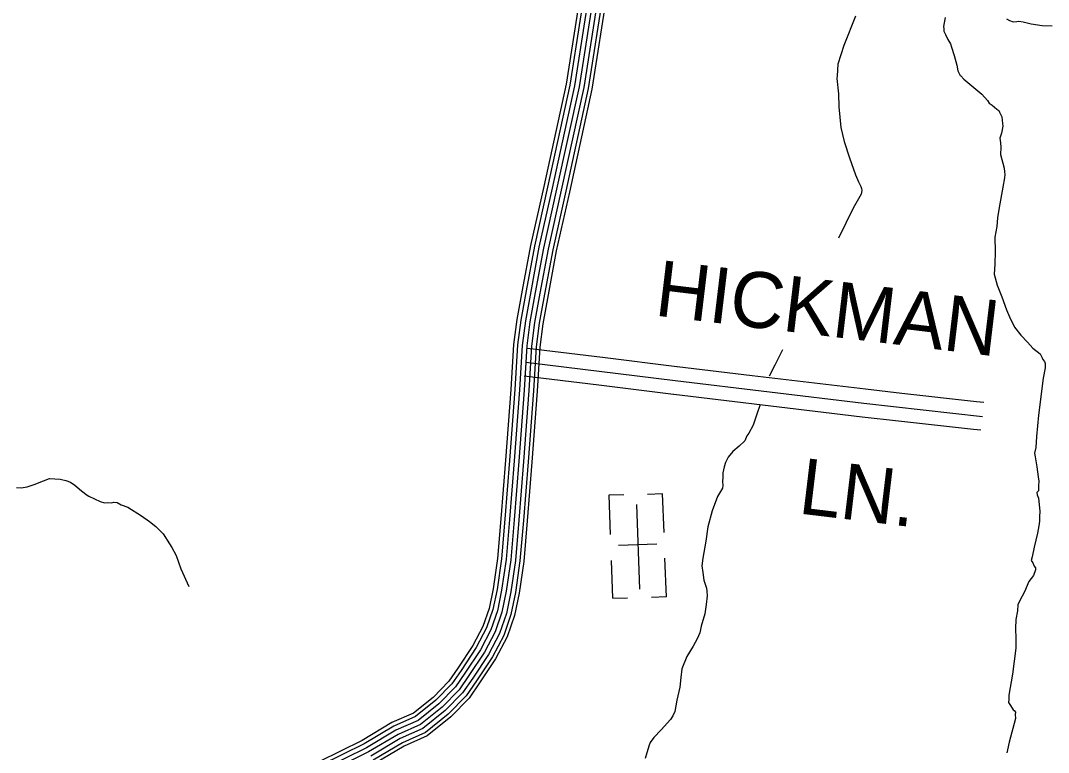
# Model space of a CAD drawing. Extents: x 1551132 to 1791609, y 378168 to 563823.
# Drawn here: x 1653929 to 1660744, y 437892 to 442743 of the extents above; entities that cross this region are included whole.
import ezdxf

# ---------------------------------------------------------------- set-up
doc = ezdxf.new("R2010")
doc.units = 0
for name, color, linetype in [('DESIGN - ROW - Right-of-Way and Easement Labels', 7, 'Continuous'), ('DESIGN - TRANSPORTATION - Text', 7, 'Continuous'), ('DESIGN - UTILITIES - Cable (Underground) with Text', 7, 'Continuous'), ('SURVEY - CENTERLINE - Preliminary Text', 7, 'Continuous'), ('SURVEY - PROPERTY - Owners', 7, 'Continuous')]:
    doc.layers.add(name, color=color, linetype=linetype)

msp = doc.modelspace()

# ---------------------------------------------------------------- linework, layer by layer
at = {"layer": 'DESIGN - TRANSPORTATION - Text'}
for points in [[(1659464.746, 442771.948), (1659388.681, 442578.526), (1659347.349, 442454.814), (1659342.482, 442376.771), (1659340.282, 442358.77), (1659353.124, 442256.493), (1659354.165, 442170.365), (1659368.623, 442034.028), (1659389.564, 441941.676), (1659424.305, 441833.148), (1659464.996, 441720.554), (1659484.454, 441674.277), (1659500.095, 441644.06), (1659503.928, 441630.001), (1659507.77, 441615.943), (1659503.503, 441591.959), (1659450.529, 441498.414), (1659352.423, 441301.576)], [(1660059.891, 442763.389), (1660049.233, 442703.421), (1660051.049, 442687.379), (1660050.891, 442673.37), (1660062.632, 442651.212), (1660078.232, 442616.994), (1660093.89, 442588.785), (1660101.64, 442566.668), (1660118.989, 442510.4), (1660136.264, 442448.131), (1660143.83, 442409.997), (1660151.622, 442391.888), (1660159.472, 442379.779), (1660163.421, 442375.729), (1660183.171, 442355.487), (1660301.91, 442256.051), (1660339.384, 442213.584), (1660351.167, 442195.425), (1660370.983, 442181.191), (1660402.649, 442154.807), (1660416.54, 442146.64), (1660420.424, 442136.59), (1660436.04, 442104.372), (1660439.54, 442060.28), (1660441.34, 442042.229), (1660432.84, 441996.27), (1660422.49, 441964.335), (1660426.132, 441932.251), (1660427.815, 441904.201), (1660427.257, 441854.141), (1660450.214, 441763.764), (1660453.939, 441739.696), (1660455.764, 441723.654), (1660453.498, 441699.645), (1660442.815, 441637.677), (1660417.348, 441503.782), (1660406.607, 441435.813), (1660401.965, 441377.787), (1660389.199, 441307.835), (1660390.124, 441211.691), (1660389.182, 441127.597), (1660384.449, 441061.562), (1660403.615, 440989.252), (1660434.698, 440910.808), (1660465.714, 440826.356), (1660485.171, 440780.079), (1660518.371, 440711.619), (1660561.703, 440657.068), (1660605.127, 440610.533), (1660640.651, 440572.091), (1660690.158, 440533.49), (1660701.85, 440507.331), (1660707.733, 440497.256), (1660717.557, 440483.122), (1660723.391, 440469.046), (1660723.166, 440449.021), (1660723.082, 440441.012), (1660710.341, 440373.061), (1660677.633, 440127.096), (1660666.075, 439987.034), (1660661.258, 439912.99), (1660652.842, 439875.031), (1660656.567, 439850.955), (1660667.817, 439784.745), (1660677.066, 439718.56), (1660680.741, 439690.476), (1660678.391, 439658.459), (1660678.033, 439626.424), (1660667.908, 439614.516), (1660669.75, 439600.482), (1660677.5, 439578.365), (1660686.499, 439490.146), (1660684.099, 439454.128), (1660685.758, 439424.069), (1660681.433, 439394.077), (1660672.908, 439346.109), (1660649.883, 439252.24), (1660637.184, 439188.296), (1660628.926, 439164.354), (1660640.734, 439148.204), (1660650.475, 439126.061), (1660658.35, 439115.961), (1660658.191, 439101.944), (1660645.783, 439064.035), (1660615.384, 439024.317), (1660586.66, 438956.54), (1660554.06, 438898.822), (1660541.761, 438870.921), (1660539.319, 438830.895), (1660528.686, 438772.935), (1660526.011, 438712.884), (1660527.278, 438646.782), (1660528.553, 438582.68), (1660506.661, 438410.701), (1660481.129, 438270.789), (1660482.812, 438242.738), (1660480.595, 438222.738), (1660492.353, 438202.579)], [(1660467.273, 442754.889), (1660485.114, 442742.681), (1660510.989, 442734.381), (1660534.98, 442736.122), (1660549.004, 442739.972), (1660576.895, 442733.656), (1660630.686, 442721.047), (1660702.476, 442710.247), (1660768.357, 442707.513)], [(1658982.007, 440561.048), (1658929.574, 440458.77), (1658893.067, 440385.727)], [(1658834.027, 440198.738), (1658808.027, 440127.67), (1658787.319, 440061.81), (1658758.753, 440008.05), (1658744.57, 439990.183), (1658732.204, 439956.274), (1658693.88, 439922.648), (1658651.539, 439887.072), (1658621.156, 439849.354), (1658602.773, 439813.512), (1658594.474, 439785.561), (1658586.04, 439745.601), (1658585.724, 439717.567), (1658583.39, 439687.55), (1658585.099, 439661.499), (1658582.899, 439643.499), (1658550.325, 439587.789), (1658515.317, 439494.045), (1658486.176, 439388.225), (1658473.118, 439292.239), (1658453.893, 439180.303), (1658445.318, 439128.335), (1658452.818, 439084.192), (1658460.243, 439034.041), (1658477.643, 438981.781), (1658479.409, 438961.739)], [(1653900.95, 439649.03), (1653932.883, 439646.671), (1653972.899, 439652.238), (1654019.006, 439667.755), (1654081.213, 439693.098), (1654121.312, 439706.681), (1654157.261, 439706.281), (1654191.193, 439703.906), (1654229.051, 439695.481), (1654260.875, 439683.114), (1654288.608, 439662.78), (1654332.148, 439626.254), (1654369.781, 439597.804), (1654382.531, 439590.587), (1654457.187, 439554.778), (1654485.061, 439546.461), (1654505.053, 439548.244), (1654530.994, 439545.961), (1654547.035, 439551.786), (1654568.96, 439547.544), (1654596.767, 439533.219), (1654640.524, 439516.71), (1654729.772, 439459.659), (1654783.296, 439423.016), (1654824.878, 439390.515), (1654874.277, 439341.906), (1654915.476, 439275.37), (1654931.184, 439251.162), (1654960.542, 439196.768), (1654991.516, 439108.308), (1655044.14, 438991.571)], [(1658479.409, 438961.739), (1658481.051, 438929.672), (1658474.409, 438871.67), (1658465.751, 438811.685), (1658440.852, 438727.85), (1658432.368, 438683.882), (1658415.944, 438644.014), (1658389.444, 438596.238), (1658346.745, 438528.619), (1658313.871, 438446.876), (1658307.23, 438388.866), (1658300.521, 438324.856), (1658279.588, 438238.978), (1658266.755, 438163.018), (1658254.464, 438135.117), (1658238.214, 438111.258), (1658177.516, 438041.84), (1658127.009, 437990.322), (1658104.676, 437958.529), (1658094.426, 437934.612), (1658069.543, 437852.777)], [(1660492.353, 438202.579), (1660510.011, 438174.345), (1660517.961, 438170.253), (1660525.811, 438158.153), (1660523.661, 438144.161), (1660525.344, 438116.101), (1660483.653, 437960.356), (1660473.087, 437908.396), (1660468.895, 437890.421)]]:
    msp.add_lwpolyline(points, dxfattribs=at)
at = {"layer": 'DESIGN - UTILITIES - Cable (Underground) with Text'}
for p, q in [((1657829.832, 439596.335), (1657839.394, 439335.787)), ((1657929.434, 439600.019), (1657830.482, 439596.36)), ((1658186.132, 439605.472), (1658086.496, 439601.863)), ((1658195.46, 439348.916), (1658186.057, 439605.431)), ((1658148.152, 439272.814), (1657894.721, 439263.378)), ((1657845.712, 439164.933), (1657854.857, 438913.627)), ((1658211.04, 438922.707), (1658201.604, 439180.688)), ((1657854.974, 438913.669), (1657953.218, 438917.32)), ((1658210.865, 438922.782), (1658111.421, 438919.064))]:
    msp.add_line(p, q, dxfattribs=at)
msp.add_lwpolyline([(1658012.987, 439535.644), (1658033.702, 438973.031)], dxfattribs=at)
at = {"layer": 'SURVEY - CENTERLINE - Preliminary Text'}
for points in [[(1657751.562, 443633.528), (1657546.149, 442320.477), (1657397.636, 441643.492), (1657310.379, 441252.223), (1657255.864, 440956.607), (1657220.006, 440760.452), (1657198.123, 440595.24), (1657179.765, 440298.573), (1657144.316, 439829.07), (1657113.433, 439441.159), (1657091.675, 439177.777), (1657062.892, 438977.056), (1657035.543, 438845.319), (1656994.552, 438727.007), (1656928.662, 438601.162), (1656828.439, 438450.175), (1656768.424, 438363.339), (1656664.376, 438257.036), (1656534.613, 438152.475), (1656391.699, 438089.89), (1656195.087, 437972.104), (1655907.569, 437830.733)], [(1657776.986, 443629.653), (1657571.432, 442315.726), (1657422.752, 441637.942), (1657335.579, 441247.09), (1657281.155, 440951.966), (1657245.414, 440756.444), (1657223.731, 440592.756), (1657205.423, 440296.815), (1657169.957, 439827.078), (1657139.066, 439439.084), (1657117.241, 439174.886), (1657088.233, 438972.614), (1657060.384, 438838.46), (1657018.227, 438716.782), (1656950.828, 438588.054), (1656849.73, 438435.758), (1656788.34, 438346.914), (1656681.693, 438237.961), (1656548.079, 438130.3), (1656403.507, 438066.981), (1656207.387, 437949.495), (1655920.56, 437808.466)], [(1657807.627, 443624.986), (1657601.915, 442310.01), (1657453.018, 441631.242), (1657365.961, 441240.898), (1657311.646, 440946.365), (1657276.047, 440751.619), (1657254.605, 440589.764), (1657236.356, 440294.69), (1657200.865, 439824.686), (1657169.965, 439436.576), (1657148.057, 439171.411), (1657118.783, 438967.255), (1657090.325, 438830.202), (1657046.759, 438704.448), (1656977.544, 438572.253), (1656875.396, 438418.366), (1656812.34, 438327.122), (1656702.567, 438214.969), (1656564.304, 438103.557), (1656417.749, 438039.381), (1656222.212, 437922.236), (1655936.227, 437781.624)], [(1657838.277, 443620.319), (1657632.397, 442304.285), (1657483.284, 441624.55), (1657396.344, 441234.715), (1657342.137, 440940.765), (1657306.679, 440746.794), (1657285.48, 440586.764), (1657267.28, 440292.565), (1657231.772, 439822.286), (1657200.864, 439434.068), (1657178.873, 439167.927), (1657149.332, 438961.897), (1657120.274, 438821.943), (1657075.292, 438692.115), (1657004.26, 438556.444), (1656901.063, 438400.982), (1656836.339, 438307.321), (1656723.442, 438191.976), (1656580.528, 438076.823), (1656431.99, 438011.772), (1656237.045, 437894.985), (1655951.893, 437754.781)], [(1657838.277, 443620.319), (1657632.397, 442304.285), (1657483.284, 441624.55), (1657396.344, 441234.715), (1657342.137, 440940.765), (1657306.679, 440746.794), (1657285.48, 440586.764), (1657267.28, 440292.565), (1657231.772, 439822.286), (1657200.864, 439434.068), (1657178.873, 439167.927), (1657149.332, 438961.897), (1657120.274, 438821.943), (1657075.292, 438692.115), (1657004.26, 438556.444), (1656901.063, 438400.982), (1656836.339, 438307.321), (1656723.442, 438191.976), (1656580.528, 438076.823), (1656431.99, 438011.772), (1656237.045, 437894.985), (1655951.893, 437754.781)], [(1657868.926, 443615.652), (1657662.88, 442298.559), (1657513.55, 441617.858), (1657426.727, 441228.531), (1657372.628, 440935.165), (1657337.312, 440741.968), (1657316.354, 440583.764), (1657298.204, 440290.44), (1657262.68, 439819.886), (1657231.764, 439431.559), (1657209.689, 439164.444), (1657179.881, 438956.538), (1657150.224, 438813.685), (1657103.825, 438679.781), (1657030.976, 438540.636), (1656926.729, 438383.598), (1656860.338, 438287.521), (1656744.316, 438168.984), (1656596.753, 438050.089), (1656446.231, 437984.163), (1656251.877, 437867.734)], [(1657899.567, 443610.986), (1657693.363, 442292.843), (1657543.816, 441611.158), (1657457.109, 441222.339), (1657403.119, 440929.565), (1657367.945, 440737.143), (1657347.228, 440580.773), (1657329.137, 440288.315), (1657293.587, 439817.494), (1657262.663, 439429.051), (1657240.505, 439160.969), (1657210.431, 438951.18), (1657180.165, 438805.426), (1657132.357, 438667.447), (1657057.692, 438524.835), (1656952.395, 438366.206), (1656884.338, 438267.729), (1656765.191, 438145.992), (1656612.977, 438023.347), (1656460.473, 437956.562), (1656266.702, 437840.475)], [(1657924, 443607.26), (1657717.662, 442288.276), (1657567.949, 441605.816), (1657481.325, 441217.406), (1657427.427, 440925.107), (1657392.361, 440733.293), (1657371.844, 440578.381), (1657353.795, 440286.623), (1657318.229, 439815.578), (1657287.296, 439427.059), (1657265.079, 439158.194), (1657234.788, 438946.913), (1657204.039, 438798.834), (1657155.115, 438657.614), (1657078.992, 438512.235), (1656972.861, 438352.347), (1656903.479, 438251.945), (1656781.832, 438127.658), (1656625.919, 438002.03), (1656471.822, 437934.545), (1656278.527, 437818.75)]]:
    msp.add_lwpolyline(points, dxfattribs=at)
at = {"layer": 'SURVEY - PROPERTY - Owners'}
for points in [[(1657290.213, 440572.056), (1657786.51, 440511.446), (1658281.056, 440451.045), (1658282.573, 440450.861), (1658779.036, 440391.227), (1659530.56, 440300.958), (1659771.313, 440274.141), (1660268.226, 440218.798), (1660316.933, 440213.373)], [(1657278.78, 440478.453), (1658269.765, 440357.426), (1659519.719, 440207.289), (1660306.5, 440119.662)], [(1657267.788, 440388.409), (1657764.077, 440327.8), (1658258.898, 440267.365), (1658260.598, 440267.165), (1659253.4, 440147.921), (1659509.286, 440117.178), (1659750.838, 440090.278), (1660247.752, 440034.935), (1660296.459, 440029.51)]]:
    msp.add_lwpolyline(points, dxfattribs=at)

# ---------------------------------------------------------------- texts
at = {"layer": 'DESIGN - ROW - Right-of-Way and Easement Labels'}
for s, rotation, p in [('HICKMAN', 353.1507806, (1658126.268, 440788.92)), ('LN.', 353.1492667, (1659079.352, 439476.888))]:
    msp.add_text(s, height=369.9915, rotation=rotation, dxfattribs=at).set_placement(p)

doc.saveas('drawing.dxf')
